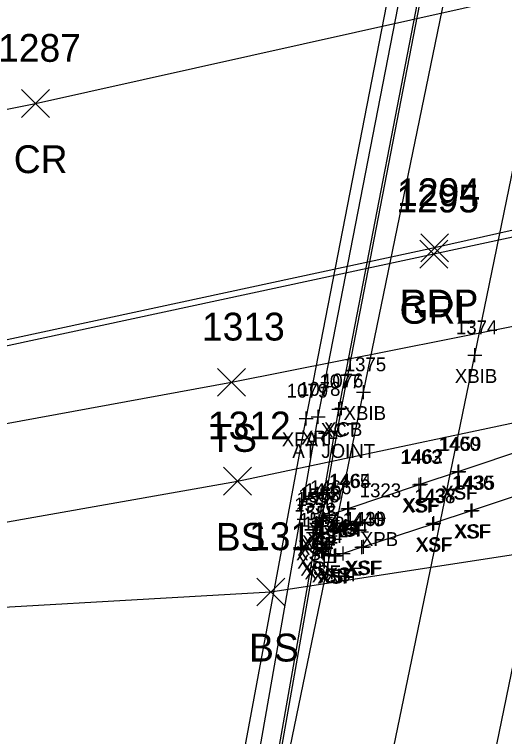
# Model space of a CAD drawing. Extents: x 1683147 to 1683637, y 416837 to 418211.
# Drawn here: x 1683280.1 to 1683315.4, y 417492.2 to 417544.1 of the extents above; entities that cross this region are included whole.
import ezdxf

# ---------------------------------------------------------------- set-up
doc = ezdxf.new("R2010")
doc.units = 0
for name, color, linetype in [('B_A', 7, 'Continuous'), ('B_C', 7, 'Continuous'), ('B_I', 7, 'Continuous'), ('B_TIC', 7, 'Continuous'), ('BB', 7, 'Continuous'), ('BDC', 7, 'Continuous'), ('BDEFAULT', 7, 'Continuous'), ('BF', 7, 'Continuous'), ('BR', 7, 'Continuous'), ('L_A', 7, 'Continuous'), ('L_I', 7, 'Continuous'), ('L_TIC', 7, 'Continuous'), ('LELB', 7, 'Continuous'), ('P_A', 7, 'Continuous'), ('P_I', 7, 'Continuous'), ('P_TIC', 7, 'Continuous'), ('PET', 7, 'Continuous'), ('PRC', 7, 'Continuous'), ('R_A', 7, 'Continuous'), ('R_I', 7, 'Continuous'), ('R_TIC', 7, 'Continuous'), ('RGR', 7, 'Continuous')]:
    doc.layers.add(name, color=color, linetype=linetype)

msp = doc.modelspace()

# ---------------------------------------------------------------- linework, layer by layer
at = {"layer": 'B_TIC'}
for p, q in [((1683313.216, 417519.604), (1683313.292, 417519.604)), ((1683305.224, 417516.944), (1683305.3, 417516.944)), ((1683303.443, 417515.718), (1683303.518, 417515.718)), ((1683303.655, 417515.782), (1683303.73, 417515.782)), ((1683301.977, 417515.177), (1683302.052, 417515.177)), ((1683301.099, 417515.048), (1683301.175, 417515.048)), ((1683312.036, 417511.218), (1683312.111, 417511.218)), ((1683312.068, 417511.232), (1683312.143, 417511.232)), ((1683309.233, 417510.287), (1683309.309, 417510.287)), ((1683309.335, 417510.339), (1683309.41, 417510.339)), ((1683304.103, 417508.554), (1683304.178, 417508.554)), ((1683304.17, 417508.576), (1683304.245, 417508.576)), ((1683312.948, 417508.426), (1683313.024, 417508.426)), ((1683313.041, 417508.445), (1683313.116, 417508.445)), ((1683302.36, 417507.902), (1683302.436, 417507.902)), ((1683302.778, 417508.108), (1683302.853, 417508.108)), ((1683306.299, 417507.885), (1683306.375, 417507.885)), ((1683301.882, 417507.523), (1683301.957, 417507.523)), ((1683301.882, 417507.523), (1683301.957, 417507.523)), ((1683302.043, 417507.66), (1683302.119, 417507.66)), ((1683310.203, 417507.466), (1683310.278, 417507.466)), ((1683310.271, 417507.519), (1683310.347, 417507.519)), ((1683301.621, 417506.863), (1683301.696, 417506.863)), ((1683301.752, 417507.27), (1683301.828, 417507.27)), ((1683301.691, 417506.254), (1683301.767, 417506.254)), ((1683301.94, 417505.765), (1683302.015, 417505.765)), ((1683305.111, 417505.801), (1683305.186, 417505.801)), ((1683305.216, 417505.834), (1683305.292, 417505.834)), ((1683302.235, 417505.5), (1683302.31, 417505.5)), ((1683302.742, 417505.264), (1683302.817, 417505.264)), ((1683303.759, 417505.339), (1683303.834, 417505.339)), ((1683303.136, 417505.178), (1683303.212, 417505.178)), ((1683303.249, 417505.203), (1683303.325, 417505.203))]:
    msp.add_line(p, q, dxfattribs=at)
for points in [[(1683313.213, 417519.104), (1683313.213, 417520.104)], [(1683312.713, 417519.604), (1683313.713, 417519.604)], [(1683305.221, 417516.444), (1683305.221, 417517.444)], [(1683304.721, 417516.944), (1683305.721, 417516.944)], [(1683303.439, 417515.218), (1683303.439, 417516.218)], [(1683303.651, 417515.282), (1683303.651, 417516.282)], [(1683301.973, 417514.677), (1683301.973, 417515.677)], [(1683302.939, 417515.718), (1683303.939, 417515.718)], [(1683303.151, 417515.782), (1683304.151, 417515.782)], [(1683301.096, 417514.548), (1683301.096, 417515.548)], [(1683301.473, 417515.177), (1683302.473, 417515.177)], [(1683300.596, 417515.048), (1683301.596, 417515.048)], [(1683312.032, 417510.718), (1683312.032, 417511.718)], [(1683312.064, 417510.732), (1683312.064, 417511.732)], [(1683311.532, 417511.218), (1683312.532, 417511.218)], [(1683311.564, 417511.232), (1683312.564, 417511.232)], [(1683309.23, 417509.787), (1683309.23, 417510.787)], [(1683309.331, 417509.839), (1683309.331, 417510.839)], [(1683308.73, 417510.287), (1683309.73, 417510.287)], [(1683308.831, 417510.339), (1683309.831, 417510.339)], [(1683304.099, 417508.054), (1683304.099, 417509.054)], [(1683304.166, 417508.076), (1683304.166, 417509.076)], [(1683312.945, 417507.926), (1683312.945, 417508.926)], [(1683313.037, 417507.945), (1683313.037, 417508.945)], [(1683302.357, 417507.402), (1683302.357, 417508.402)], [(1683302.774, 417507.608), (1683302.774, 417508.608)], [(1683303.599, 417508.554), (1683304.599, 417508.554)], [(1683303.666, 417508.576), (1683304.666, 417508.576)], [(1683306.296, 417507.385), (1683306.296, 417508.385)], [(1683312.445, 417508.426), (1683313.445, 417508.426)], [(1683312.537, 417508.445), (1683313.537, 417508.445)], [(1683301.857, 417507.902), (1683302.857, 417507.902)], [(1683301.878, 417507.023), (1683301.878, 417508.023)], [(1683301.878, 417507.023), (1683301.878, 417508.023)], [(1683302.04, 417507.16), (1683302.04, 417508.16)], [(1683302.274, 417508.108), (1683303.274, 417508.108)], [(1683305.796, 417507.885), (1683306.796, 417507.885)], [(1683310.199, 417506.966), (1683310.199, 417507.966)], [(1683310.268, 417507.019), (1683310.268, 417508.019)], [(1683301.378, 417507.523), (1683302.378, 417507.523)], [(1683301.378, 417507.523), (1683302.378, 417507.523)], [(1683301.54, 417507.66), (1683302.54, 417507.66)], [(1683301.618, 417506.363), (1683301.618, 417507.363)], [(1683301.749, 417506.77), (1683301.749, 417507.77)], [(1683309.699, 417507.466), (1683310.699, 417507.466)], [(1683309.768, 417507.519), (1683310.768, 417507.519)], [(1683301.118, 417506.863), (1683302.118, 417506.863)], [(1683301.249, 417507.27), (1683302.249, 417507.27)], [(1683301.688, 417505.754), (1683301.688, 417506.754)], [(1683301.936, 417505.265), (1683301.936, 417506.265)], [(1683305.107, 417505.301), (1683305.107, 417506.301)], [(1683305.213, 417505.334), (1683305.213, 417506.334)], [(1683301.188, 417506.254), (1683302.188, 417506.254)], [(1683301.436, 417505.765), (1683302.436, 417505.765)], [(1683302.231, 417505), (1683302.231, 417506)], [(1683302.738, 417504.764), (1683302.738, 417505.764)], [(1683303.755, 417504.839), (1683303.755, 417505.839)], [(1683304.607, 417505.801), (1683305.607, 417505.801)], [(1683304.713, 417505.834), (1683305.713, 417505.834)], [(1683301.731, 417505.5), (1683302.731, 417505.5)], [(1683302.238, 417505.264), (1683303.238, 417505.264)], [(1683303.133, 417504.678), (1683303.133, 417505.678)], [(1683303.246, 417504.703), (1683303.246, 417505.703)], [(1683303.255, 417505.339), (1683304.255, 417505.339)], [(1683302.633, 417505.178), (1683303.633, 417505.178)], [(1683302.746, 417505.203), (1683303.746, 417505.203)]]:
    msp.add_lwpolyline(points, dxfattribs=at)
at = {"layer": 'BB'}
for points in [[(1683309.186, 417464.354), (1683321.096, 417522.255), (1683338.804, 417607.952), (1683349.063, 417657.849)], [(1683301.278, 417461.805), (1683313.213, 417519.604), (1683330.806, 417605.15), (1683341.02, 417655.206)], [(1683293.295, 417459.142), (1683305.221, 417516.944), (1683322.812, 417602.383), (1683333.052, 417652.523)]]:
    msp.add_lwpolyline(points, dxfattribs=at)
at = {"layer": 'BDC'}
for points in [[(1683293.606, 417457.004), (1683297.933, 417483.396), (1683303.651, 417515.782), (1683310.43, 417550.936), (1683319.486, 417594.409), (1683325.369, 417620.597), (1683333.615, 417654.761)], [(1683293.283, 417456.91), (1683297.758, 417483.397), (1683303.439, 417515.718), (1683310.273, 417550.995), (1683319.259, 417594.072), (1683325.276, 417620.725), (1683333.387, 417654.646)]]:
    msp.add_lwpolyline(points, dxfattribs=at)
at = {"layer": 'BDEFAULT'}
for points in [[(1683343.05, 417521.439), (1683342.699, 417521.474), (1683342.257, 417521.384), (1683335.818, 417519.23), (1683335.778, 417519.216), (1683327.931, 417516.576), (1683327.86, 417516.543), (1683325.169, 417515.648), (1683325.081, 417515.608), (1683319.996, 417513.899), (1683319.939, 417513.882), (1683317.241, 417512.976), (1683317.151, 417512.94), (1683312.064, 417511.232), (1683312.032, 417511.218), (1683309.331, 417510.339), (1683309.23, 417510.287), (1683304.166, 417508.576), (1683304.099, 417508.554), (1683302.774, 417508.108), (1683302.357, 417507.902), (1683302.04, 417507.66), (1683301.878, 417507.523)], [(1683318.122, 417510.144), (1683313.037, 417508.445), (1683312.945, 417508.426), (1683310.268, 417507.519), (1683310.199, 417507.466), (1683305.213, 417505.834), (1683305.107, 417505.801), (1683303.755, 417505.339), (1683303.246, 417505.203), (1683303.133, 417505.178), (1683302.738, 417505.264), (1683302.231, 417505.5), (1683301.936, 417505.765), (1683301.688, 417506.254), (1683301.618, 417506.863), (1683301.749, 417507.27), (1683301.878, 417507.523)]]:
    msp.add_lwpolyline(points, dxfattribs=at)
at = {"layer": 'BF'}
msp.add_lwpolyline([(1683290.891, 417457.431), (1683295.203, 417483.369), (1683301.096, 417515.048), (1683308.112, 417551.126), (1683316.53, 417593.209), (1683322.67, 417620.925), (1683330.916, 417655.559)], dxfattribs=at)
at = {"layer": 'BR'}
msp.add_lwpolyline([(1683290.803, 417448.811), (1683292.09, 417457.121), (1683296.401, 417483.47), (1683301.973, 417515.177), (1683308.968, 417551.101), (1683317.909, 417594.057), (1683323.913, 417620.951), (1683332.125, 417655.111), (1683334.513, 417664.825)], dxfattribs=at)
at = {"layer": 'L_TIC'}
for points in [[(1683294.742, 417516.653), (1683296.742, 417518.653)], [(1683296.742, 417516.653), (1683294.742, 417518.653)], [(1683295.171, 417509.545), (1683297.171, 417511.545)], [(1683297.171, 417509.545), (1683295.171, 417511.545)], [(1683297.559, 417501.586), (1683299.559, 417503.586)], [(1683299.559, 417501.586), (1683297.559, 417503.586)]]:
    msp.add_lwpolyline(points, dxfattribs=at)
at = {"layer": 'LELB'}
for points in [[(1683205.058, 417500.966), (1683236.725, 417507.171), (1683266.627, 417512.319), (1683295.742, 417517.653), (1683322.975, 417523.071), (1683351.626, 417530.069)], [(1683205.591, 417497.875), (1683237.075, 417504.337), (1683268.914, 417505.721), (1683296.171, 417510.545), (1683323.546, 417516.347), (1683350.433, 417523.399)], [(1683205.213, 417492.626), (1683239.174, 417495.288), (1683270.177, 417500.965), (1683298.559, 417502.586), (1683327.653, 417507.076), (1683349.696, 417514.294)]]:
    msp.add_lwpolyline(points, dxfattribs=at)
at = {"layer": 'P_TIC'}
for points in [[(1683280.666, 417536.682), (1683282.666, 417538.682)], [(1683282.666, 417536.682), (1683280.666, 417538.682)], [(1683309.333, 417526.312), (1683311.333, 417528.312)], [(1683311.333, 417526.312), (1683309.333, 417528.312)]]:
    msp.add_lwpolyline(points, dxfattribs=at)
at = {"layer": 'PET'}
msp.add_lwpolyline([(1683351.521, 417537.139), (1683327.502, 417531.164), (1683310.333, 417527.312), (1683275.263, 417519.769), (1683242.13, 417513.342), (1683204.728, 417507.24)], dxfattribs=at)
at = {"layer": 'PRC'}
msp.add_lwpolyline([(1683202.452, 417523.569), (1683242.343, 417529.845), (1683281.666, 417537.682), (1683320.124, 417546.282), (1683360.503, 417556.965)], dxfattribs=at)
at = {"layer": 'R_TIC'}
for points in [[(1683309.27, 417525.858), (1683311.27, 417527.858)], [(1683311.27, 417525.858), (1683309.27, 417527.858)]]:
    msp.add_lwpolyline(points, dxfattribs=at)
at = {"layer": 'RGR'}
msp.add_lwpolyline([(1683351.634, 417536.475), (1683327.504, 417530.568), (1683310.27, 417526.858), (1683275.284, 417519.336), (1683242.138, 417513.085), (1683204.773, 417506.832)], dxfattribs=at)

# ---------------------------------------------------------------- texts
at = {"layer": 'B_A'}
for s, p in [('XBIB', (1683311.784, 417517.604)), ('XBIB', (1683303.792, 417514.944)), ('XCT', (1683302.16, 417513.718)), ('XCB', (1683302.387, 417513.782)), ('XFAT', (1683299.352, 417513.048)), ('XRF', (1683300.733, 417513.177)), ('XSF', (1683310.792, 417509.218)), ('XSF', (1683310.824, 417509.232)), ('XSF', (1683307.99, 417508.287)), ('XSF', (1683308.091, 417508.339)), ('XSF', (1683302.859, 417506.554)), ('XSF', (1683302.926, 417506.576)), ('XSF', (1683311.705, 417506.426)), ('XSF', (1683311.797, 417506.445)), ('XSF', (1683301.117, 417505.902)), ('XSF', (1683301.534, 417506.108)), ('XPB', (1683305.032, 417505.885)), ('XSF', (1683300.508, 417505.27)), ('XSF', (1683300.638, 417505.523)), ('XSF', (1683300.638, 417505.523)), ('XSF', (1683300.799, 417505.66)), ('XSF', (1683308.959, 417505.466)), ('XSF', (1683309.027, 417505.519)), ('XSF', (1683300.377, 417504.863)), ('XSF', (1683300.448, 417504.254)), ('XSF', (1683300.696, 417503.765)), ('XSF', (1683303.867, 417503.801)), ('XSF', (1683303.973, 417503.834)), ('XSF', (1683300.991, 417503.5)), ('XSF', (1683301.498, 417503.264)), ('XSF', (1683301.892, 417503.178)), ('XSF', (1683302.006, 417503.203)), ('XSF', (1683302.515, 417503.339))]:
    msp.add_text(s, height=1, dxfattribs=at).set_placement(p)
at = {"layer": 'B_C'}
msp.add_text('AT JOINT', height=1, dxfattribs=at).set_placement((1683300.112, 417512.218))
at = {"layer": 'B_I'}
for s, p in [('1374', (1683311.866, 417521.104)), ('1375', (1683303.874, 417518.444)), ('1077', (1683302.053, 417517.218)), ('1076', (1683302.238, 417517.282)), ('1078', (1683300.587, 417516.677)), ('1079', (1683299.706, 417516.548)), ('1460', (1683310.619, 417512.718)), ('1459', (1683310.714, 417512.732)), ('1463', (1683307.86, 417511.787)), ('1462', (1683307.961, 417511.839)), ('1465', (1683302.729, 417510.054)), ('1464', (1683302.796, 417510.076)), ('1436', (1683311.571, 417509.926)), ('1435', (1683311.691, 417509.945)), ('1467', (1683300.987, 417509.402)), ('1466', (1683301.377, 417509.608)), ('1558', (1683300.532, 417509.023)), ('1558', (1683300.532, 417509.023)), ('1468', (1683300.67, 417509.16)), ('1323', (1683304.95, 417509.385)), ('1438', (1683308.853, 417508.966)), ('1437', (1683308.921, 417509.019)), ('1556', (1683300.244, 417508.363)), ('1557', (1683300.402, 417508.77)), ('1555', (1683300.341, 417507.754)), ('1439', (1683303.862, 417507.334)), ('1554', (1683300.59, 417507.265)), ('1553', (1683300.885, 417507)), ('1441', (1683302.693, 417506.839)), ('1440', (1683303.718, 417507.301)), ('1552', (1683301.392, 417506.764)), ('1443', (1683301.786, 417506.678)), ('1442', (1683301.899, 417506.703))]:
    msp.add_text(s, height=1, dxfattribs=at).set_placement(p)
at = {"layer": 'L_A'}
for s, p in [('TS', (1683294.152, 417512.653)), ('BS', (1683294.612, 417505.545)), ('BS', (1683297, 417497.586))]:
    msp.add_text(s, height=2, dxfattribs=at).set_placement(p)
at = {"layer": 'L_I'}
for s, p in [('1313', (1683293.616, 417520.653)), ('1312', (1683294.045, 417513.545)), ('1311', (1683297, 417505.586))]:
    msp.add_text(s, height=2, dxfattribs=at).set_placement(p)
at = {"layer": 'P_A'}
for s, p in [('CR', (1683280.099, 417532.682)), ('RDP', (1683307.822, 417522.312))]:
    msp.add_text(s, height=2, dxfattribs=at).set_placement(p)
at = {"layer": 'P_I'}
for s, p in [('1287', (1683278.973, 417540.682)), ('1294', (1683307.641, 417530.312))]:
    msp.add_text(s, height=2, dxfattribs=at).set_placement(p)
at = {"layer": 'R_A'}
msp.add_text('GRL', height=2, dxfattribs=at).set_placement((1683307.813, 417521.858))
at = {"layer": 'R_I'}
msp.add_text('1295', height=2, dxfattribs=at).set_placement((1683307.577, 417529.858))

doc.saveas('drawing.dxf')
